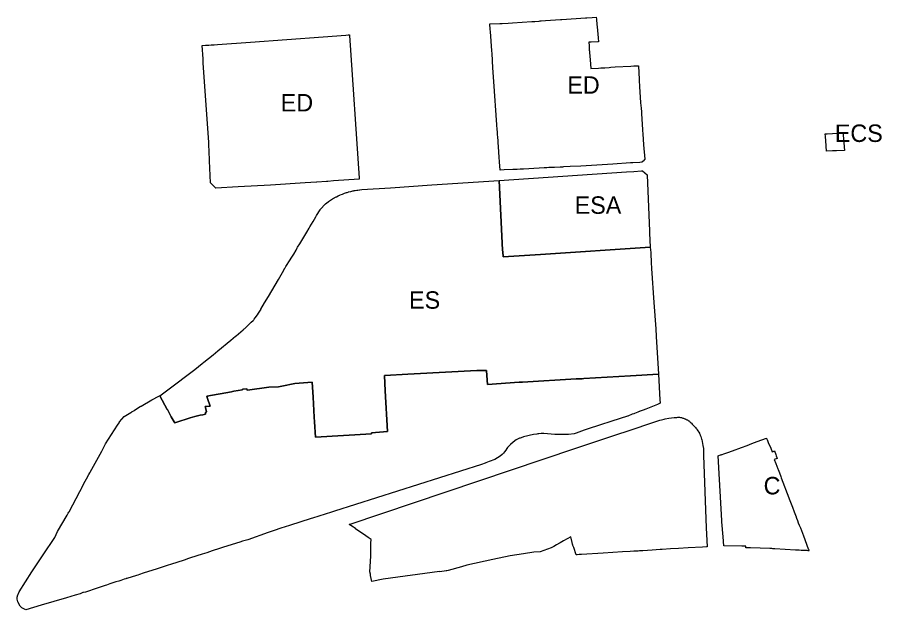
# Model space of a CAD drawing. Extents: x 603332 to 610661, y 4407453 to 4413433.
# Drawn here: x 607136 to 607730, y 4411318 to 4411725 of the extents above; entities that cross this region are included whole.
import ezdxf

# ---------------------------------------------------------------- set-up
doc = ezdxf.new("R2010")
doc.units = 0
for name, color, linetype in [('Sistema General-Equipament Públic Cementiri', 7, 'Continuous'), ('Sistema General-Equipament Públic Docent', 7, 'Continuous'), ('Sistema General-Equipament Públic Esportiu', 7, 'Continuous'), ('Sistema General-Equipament Públic Sanitari-Assistencial', 7, 'Continuous'), ('Sistema General-Equipament Públic Socio-cultural', 7, 'Continuous'), ('Sistema General-Espai Lliure Públic', 7, 'Continuous')]:
    doc.layers.add(name, color=color, linetype=linetype)

msp = doc.modelspace()

# ---------------------------------------------------------------- linework, layer by layer
at = {"layer": 'Sistema General-Equipament Públic Cementiri'}
msp.add_lwpolyline([(607668.26, 4411389.42), (607668.72, 4411388.22), (607669.92, 4411385.07), (607671.21, 4411381.68), (607671.37, 4411381.29), (607671.57, 4411380.76), (607671.58, 4411380.73), (607671.59, 4411380.69), (607671.63, 4411380.6), (607672.19, 4411379.13), (607672.78, 4411377.6), (607673.24, 4411376.38), (607673.35, 4411376.09), (607673.47, 4411375.79), (607674.17, 4411373.96), (607676.25, 4411368.51), (607679.65, 4411359.62), (607679.77, 4411359.3), (607680.01, 4411358.68), (607680.11, 4411358.4), (607680.14, 4411358.35), (607680.15, 4411358.32), (607679.74, 4411358.34), (607679.73, 4411358.34), (607679.69, 4411358.34), (607679.63, 4411358.34), (607679.44, 4411358.35), (607678.77, 4411358.38), (607676.82, 4411358.46), (607675.36, 4411358.53), (607675.31, 4411358.53), (607675.25, 4411358.53), (607675.06, 4411358.54), (607674.93, 4411358.55), (607674.84, 4411358.55), (607673.45, 4411358.64), (607670.81, 4411358.8), (607656.64, 4411359.66), (607656.59, 4411359.66), (607656.56, 4411359.66), (607656.45, 4411359.67), (607656.42, 4411359.67), (607656.41, 4411359.67), (607656.41, 4411359.67), (607655.31, 4411359.71), (607654.49, 4411359.74), (607653.2, 4411359.78), (607639.79, 4411360.25), (607639.39, 4411360.25), (607639.09, 4411360.26), (607639.07, 4411360.26), (607639.05, 4411360.26), (607639.03, 4411360.26), (607638.62, 4411360.26), (607636.73, 4411360.29), (607636.62, 4411360.29), (607636.62, 4411360.4), (607636.62, 4411360.66), (607636.63, 4411361.39), (607636.62, 4411361.39), (607636.6, 4411361.39), (607636.6, 4411361.39), (607636.49, 4411361.39), (607636.42, 4411361.39), (607636.4, 4411361.39), (607636.3, 4411361.39), (607636.05, 4411361.4), (607635.17, 4411361.41), (607634.36, 4411361.41), (607633.87, 4411361.42), (607621.48, 4411361.67), (607621.03, 4411367.87), (607620.29, 4411378.21), (607620.29, 4411378.23), (607620.28, 4411378.26), (607620.28, 4411378.31), (607620.25, 4411379.05), (607618.56, 4411407.27), (607617.66, 4411423.64), (607618.11, 4411423.78), (607619.33, 4411424.16), (607619.41, 4411424.18), (607619.47, 4411424.2), (607619.62, 4411424.25), (607620.26, 4411424.44), (607620.31, 4411424.46), (607621.56, 4411424.84), (607624.41, 4411425.9), (607627.44, 4411427.03), (607633.8, 4411429.4), (607637.49, 4411430.78), (607640.76, 4411432), (607644.38, 4411433.35), (607650.9, 4411435.78), (607650.99, 4411435.56), (607651.22, 4411435.02), (607651.28, 4411434.88), (607652.15, 4411432.77), (607653.82, 4411428.75), (607654.82, 4411426.34), (607655.15, 4411426.47), (607655.39, 4411426.57), (607655.95, 4411426.8), (607656.13, 4411426.87), (607656.31, 4411426.94), (607657.22, 4411424.52), (607657.56, 4411423.6), (607657.98, 4411422.46), (607658.23, 4411421.8), (607656.21, 4411421.12), (607657.33, 4411418.18), (607658.67, 4411414.63), (607658.85, 4411414.17), (607659.72, 4411411.86), (607660.7, 4411409.3), (607661.05, 4411408.36), (607666.27, 4411394.62), (607666.54, 4411393.91)], close=True, dxfattribs=at)
at = {"layer": 'Sistema General-Equipament Públic Docent'}
for points in [[(607562.79, 4411691.82), (607563.3, 4411682.32), (607563.34, 4411681.68), (607563.41, 4411680.54), (607563.52, 4411678.75), (607563.58, 4411677.87), (607563.6, 4411677.53), (607563.6, 4411677.5), (607564.34, 4411666.39), (607564.64, 4411662.64), (607564.84, 4411660.06), (607564.91, 4411658.93), (607565.6, 4411647.69), (607565.63, 4411647.34), (607565.82, 4411644.87), (607566.37, 4411637.4), (607567.13, 4411627.65), (607565.99, 4411626.29), (607565.47, 4411625.66), (607565.35, 4411625.51), (607565.26, 4411625.41), (607565.25, 4411625.41), (607565.17, 4411625.4), (607563.83, 4411625.33), (607559.03, 4411625.05), (607558.42, 4411625.01), (607557.45, 4411624.95), (607545.32, 4411624.19), (607537.89, 4411623.72), (607523.27, 4411622.83), (607515.95, 4411622.43), (607511.22, 4411622.18), (607510.72, 4411622.15), (607509.04, 4411622.06), (607505.16, 4411621.93), (607505.09, 4411621.93), (607505, 4411621.92), (607504.14, 4411621.88), (607503.25, 4411621.84), (607501.18, 4411621.73), (607499.85, 4411621.66), (607499.21, 4411621.62), (607498.03, 4411621.56), (607487.41, 4411620.88), (607483.81, 4411620.72), (607482.93, 4411620.68), (607482.63, 4411620.67), (607482.6, 4411620.67), (607481.5, 4411620.62), (607479.41, 4411620.53), (607478.22, 4411620.48), (607476.42, 4411620.4), (607470.59, 4411620.14), (607467.71, 4411620.02), (607467.3, 4411625.61), (607467.06, 4411628.93), (607467.04, 4411629.14), (607467.04, 4411629.16), (607467.04, 4411629.21), (607467.02, 4411629.42), (607466.85, 4411631.85), (607466.49, 4411636.69), (607466.4, 4411638.22), (607466.29, 4411640.15), (607466.27, 4411640.37), (607466.27, 4411640.41), (607466.11, 4411642.41), (607465.93, 4411644.73), (607465.81, 4411646.34), (607465.68, 4411647.98), (607465.5, 4411651.13), (607463.45, 4411681.02), (607462.81, 4411690.28), (607462.13, 4411700.26), (607462, 4411702.1), (607461.09, 4411715.36), (607460.83, 4411716.76), (607460.65, 4411720.54), (607467.59, 4411720.86), (607468.11, 4411720.85), (607468.93, 4411720.84), (607469, 4411720.84), (607469.01, 4411720.84), (607473.34, 4411721.08), (607476.18, 4411721.28), (607489.46, 4411722.19), (607489.81, 4411722.22), (607491.48, 4411722.33), (607494.62, 4411722.54), (607495.24, 4411722.58), (607495.89, 4411722.63), (607495.98, 4411722.63), (607498.94, 4411722.83), (607509.15, 4411723.52), (607510.09, 4411723.58), (607510.2, 4411723.59), (607526.33, 4411724.66), (607526.44, 4411724.67), (607527.39, 4411724.72), (607531.11, 4411724.95), (607533.84, 4411725.12), (607533.96, 4411723.87), (607534.1, 4411722.43), (607534.2, 4411721.41), (607534.32, 4411720.2), (607534.47, 4411718.63), (607535.22, 4411710.93), (607535.47, 4411708.35), (607535.13, 4411708.33), (607535.09, 4411708.33), (607534.79, 4411708.32), (607530.38, 4411708.11), (607528.69, 4411707.93), (607528.84, 4411705.41), (607528.97, 4411703.25), (607529.05, 4411702.27), (607529.06, 4411702.04), (607529.15, 4411700.93), (607529.54, 4411695.89), (607530.01, 4411689.83), (607535.44, 4411690.19), (607537.03, 4411690.29), (607539.68, 4411690.47), (607542.73, 4411690.67), (607543.83, 4411690.75), (607546.72, 4411690.94), (607557.58, 4411691.53), (607559.63, 4411691.67), (607559.72, 4411691.67), (607559.75, 4411691.67), (607560.73, 4411691.74), (607561.06, 4411691.75)], [(607341.74, 4411611.82), (607341.53, 4411611.81), (607333.63, 4411611.29), (607309.9, 4411609.74), (607287.46, 4411608.53), (607272.21, 4411607.7), (607268.59, 4411611.25), (607267.88, 4411626.39), (607267.55, 4411633.38), (607267.39, 4411636.95), (607267.33, 4411638.07), (607267.29, 4411638.91), (607263.59, 4411693.9), (607263.59, 4411693.92), (607263.42, 4411696.45), (607262.8, 4411705.68), (607265.01, 4411705.84), (607266.34, 4411705.94), (607267.43, 4411706.02), (607269.01, 4411706.13), (607269.04, 4411706.13), (607269.18, 4411706.14), (607269.42, 4411706.16), (607270.47, 4411706.24), (607270.8, 4411706.26), (607270.84, 4411706.26), (607271.07, 4411706.28), (607273.46, 4411706.46), (607296.11, 4411708.1), (607346.13, 4411711.74), (607361.68, 4411712.87), (607363.18, 4411712.98), (607363.4, 4411713), (607363.44, 4411713), (607363.54, 4411713.01), (607363.79, 4411713.03), (607364.14, 4411713.06), (607364.16, 4411713.06), (607364.19, 4411713.06), (607364.22, 4411712.7), (607364.22, 4411712.64), (607370.81, 4411614.38), (607370.82, 4411614.09), (607370.85, 4411613.73), (607353.16, 4411612.57), (607349.26, 4411612.31), (607348.42, 4411612.26)]]:
    msp.add_lwpolyline(points, close=True, dxfattribs=at)
at = {"layer": 'Sistema General-Equipament Públic Esportiu'}
msp.add_lwpolyline([(607570.95, 4411567.15), (607571.24, 4411563.39), (607571.29, 4411562.65), (607571.65, 4411556.59), (607571.6, 4411556.59), (607571.88, 4411552.43), (607573.44, 4411529.06), (607574.77, 4411510.81), (607575.07, 4411505.67), (607576.6, 4411479.75), (607557.26, 4411478.49), (607525.32, 4411476.72), (607524.15, 4411476.59), (607519.94, 4411476.43), (607483, 4411474.27), (607480.92, 4411474.12), (607458.93, 4411472.72), (607458.47, 4411478.9), (607458.26, 4411482.29), (607451.77, 4411482.14), (607408.49, 4411479.88), (607404.33, 4411479.67), (607388.51, 4411478.84), (607388.13, 4411478.82), (607388.7, 4411468.25), (607390.21, 4411440.25), (607379.27, 4411439.48), (607379.36, 4411438.69), (607340.66, 4411436.48), (607340.07, 4411446.9), (607339.89, 4411450.16), (607339.11, 4411463.87), (607338.51, 4411474.31), (607326.47, 4411473.32), (607324.35, 4411472.76), (607319.78, 4411471.86), (607315.4, 4411471), (607308.67, 4411470.84), (607293.95, 4411468.74), (607293.19, 4411469.68), (607290.54, 4411469.34), (607290.57, 4411468.93), (607284.6, 4411467.98), (607283.76, 4411467.72), (607282.93, 4411467.58), (607265.96, 4411464.59), (607266.49, 4411462.93), (607268.36, 4411457.71), (607264.83, 4411457.4), (607265.83, 4411453.96), (607265.83, 4411453.95), (607265.19, 4411453.1), (607265.15, 4411452.59), (607265.1, 4411452.11), (607263.21, 4411451.8), (607261.39, 4411451.5), (607257.86, 4411450.56), (607254.67, 4411449.71), (607244.64, 4411446.46), (607243.99, 4411446.24), (607243.48, 4411447.02), (607241.55, 4411450.48), (607238.86, 4411455.32), (607238.85, 4411455.32), (607238.83, 4411455.35), (607238.8, 4411455.41), (607233.59, 4411464.82), (607239.22, 4411469.04), (607257.7, 4411482.88), (607262.72, 4411486.95), (607264.06, 4411488.04), (607270.31, 4411493.11), (607273.67, 4411495.87), (607282.49, 4411503.11), (607285.77, 4411505.8), (607286.19, 4411506.16), (607287.71, 4411507.45), (607290.92, 4411510.17), (607291.68, 4411510.82), (607292.11, 4411511.18), (607296.52, 4411515.47), (607297.8, 4411516.7), (607298.3, 4411517.17), (607298.51, 4411517.45), (607299.23, 4411518.4), (607300.9, 4411520.59), (607301.57, 4411521.65), (607302.93, 4411523.8), (607303.08, 4411524.05), (607303.26, 4411524.33), (607305.78, 4411528.67), (607308.39, 4411533.15), (607315.22, 4411544.9), (607318.02, 4411549.7), (607319.45, 4411552.16), (607319.48, 4411552.22), (607319.52, 4411552.29), (607319.53, 4411552.31), (607319.54, 4411552.32), (607319.84, 4411552.77), (607319.9, 4411552.86), (607319.9, 4411552.86), (607319.95, 4411552.93), (607320.17, 4411553.27), (607320.45, 4411553.69), (607323.3, 4411558.36), (607324.04, 4411559.57), (607325.74, 4411562.34), (607327.34, 4411564.89), (607328.16, 4411566.54), (607328.45, 4411567.02), (607329.87, 4411569.36), (607333.3, 4411575.04), (607334.71, 4411577.38), (607336.29, 4411580.02), (607336.92, 4411581.06), (607339.08, 4411584.66), (607340.9, 4411587.97), (607341.45, 4411588.82), (607343.93, 4411592.67), (607344.03, 4411592.83), (607344.04, 4411592.84), (607344.27, 4411593.11), (607347.37, 4411596.62), (607347.39, 4411596.63), (607347.57, 4411596.78), (607348.57, 4411597.57), (607349.35, 4411598.14), (607349.72, 4411598.41), (607349.8, 4411598.47), (607351.06, 4411599.34), (607351.83, 4411599.83), (607352.28, 4411600.11), (607352.35, 4411600.16), (607352.36, 4411600.16), (607352.41, 4411600.19), (607353.42, 4411600.79), (607353.53, 4411600.85), (607353.58, 4411600.88), (607353.67, 4411600.94), (607354.94, 4411601.62), (607355.02, 4411601.66), (607355.02, 4411601.67), (607355.02, 4411601.67), (607355.13, 4411601.72), (607356.39, 4411602.35), (607356.69, 4411602.49), (607357.5, 4411602.86), (607357.78, 4411602.99), (607359.2, 4411603.57), (607360.63, 4411604.11), (607362.08, 4411604.6), (607362.53, 4411604.74), (607363.28, 4411604.96), (607363.55, 4411605.04), (607365.03, 4411605.43), (607366.52, 4411605.76), (607366.89, 4411605.83), (607367.26, 4411605.9), (607368.02, 4411606.05), (607369.12, 4411606.22), (607369.46, 4411606.27), (607369.54, 4411606.28), (607369.6, 4411606.29), (607369.9, 4411606.33), (607371.06, 4411606.46), (607371.1, 4411606.47), (607371.33, 4411606.49), (607372.58, 4411606.59), (607392.29, 4411607.91), (607420.86, 4411609.83), (607466.98, 4411612.91), (607469.39, 4411565.04), (607469.47, 4411563.86), (607469.69, 4411560.44), (607495.37, 4411562.09)], close=True, dxfattribs=at)
at = {"layer": 'Sistema General-Equipament Públic Sanitari-Assistencial'}
msp.add_lwpolyline([(607568.79, 4411616.73), (607570.45, 4411578.09), (607570.7, 4411570.59), (607570.74, 4411569.85), (607570.74, 4411569.82), (607570.78, 4411569.33), (607570.89, 4411567.87), (607570.95, 4411567.15), (607495.37, 4411562.09), (607469.69, 4411560.44), (607469.47, 4411563.86), (607469.39, 4411565.04), (607466.98, 4411612.91), (607554.67, 4411618.79), (607559.64, 4411619.12), (607564.92, 4411619.48), (607565.67, 4411619.53)], close=True, dxfattribs=at)
at = {"layer": 'Sistema General-Equipament Públic Socio-cultural'}
msp.add_lwpolyline([(607692.15, 4411633.02), (607692.15, 4411633.03), (607691.61, 4411640.09), (607691.38, 4411643.22), (607691.25, 4411644.91), (607692.57, 4411644.99), (607703.54, 4411645.75), (607703.54, 4411645.74), (607703.6, 4411644.89), (607703.66, 4411644.12), (607704.48, 4411633.56), (607699.04, 4411633.32), (607696.78, 4411633.23), (607696.18, 4411633.2)], close=True, dxfattribs=at)
at = {"layer": 'Sistema General-Espai Lliure Públic'}
for points in [[(607181.1, 4411329.54), (607180.99, 4411329.51), (607180.84, 4411329.48), (607178.9, 4411328.78), (607175.52, 4411327.78), (607169.44, 4411325.99), (607152.19, 4411320.91), (607141.47, 4411317.75), (607138.9, 4411319.12), (607137.68, 4411320.23), (607136.13, 4411323.14), (607135.67, 4411325.11), (607135.69, 4411326), (607135.7, 4411326.35), (607135.82, 4411327.04), (607135.86, 4411327.28), (607137.05, 4411330.01), (607145.61, 4411343.85), (607147.47, 4411346.49), (607149.86, 4411349.88), (607153.49, 4411355.39), (607161.42, 4411367.45), (607163.38, 4411371.57), (607169.93, 4411382.65), (607170.74, 4411384.16), (607171.07, 4411384.78), (607171.24, 4411385.09), (607178.64, 4411398.93), (607179.61, 4411400.71), (607179.88, 4411401.21), (607179.9, 4411401.24), (607179.92, 4411401.28), (607182.46, 4411406.1), (607183.37, 4411407.81), (607184.92, 4411410.75), (607185.46, 4411411.78), (607185.7, 4411412.27), (607193.72, 4411426.73), (607193.73, 4411426.75), (607193.79, 4411426.87), (607194.63, 4411428.54), (607196.32, 4411431.88), (607204.5, 4411444.7), (607205.63, 4411446.3), (607205.85, 4411446.61), (607205.89, 4411446.66), (607206.01, 4411446.83), (607209.17, 4411450.5), (607213.7, 4411453.31), (607214.24, 4411453.64), (607214.48, 4411453.79), (607214.64, 4411453.89), (607214.74, 4411453.95), (607215.74, 4411454.58), (607216.08, 4411454.8), (607218.44, 4411456.28), (607220.23, 4411457.41), (607220.55, 4411457.6), (607220.57, 4411457.62), (607220.57, 4411457.62), (607220.69, 4411457.69), (607220.82, 4411457.76), (607228.28, 4411462.04), (607233.1, 4411464.56), (607233.47, 4411464.75), (607233.57, 4411464.81), (607233.57, 4411464.81), (607233.59, 4411464.82), (607238.8, 4411455.41), (607238.83, 4411455.35), (607238.85, 4411455.32), (607238.86, 4411455.32), (607241.55, 4411450.48), (607243.48, 4411447.02), (607243.99, 4411446.24), (607244.64, 4411446.46), (607254.67, 4411449.71), (607257.86, 4411450.56), (607261.39, 4411451.5), (607263.21, 4411451.8), (607265.1, 4411452.11), (607265.15, 4411452.59), (607265.19, 4411453.1), (607265.83, 4411453.95), (607265.83, 4411453.96), (607264.83, 4411457.4), (607268.36, 4411457.71), (607266.49, 4411462.93), (607265.96, 4411464.59), (607282.93, 4411467.58), (607283.76, 4411467.72), (607284.6, 4411467.98), (607290.57, 4411468.93), (607290.54, 4411469.34), (607293.19, 4411469.68), (607293.95, 4411468.74), (607308.67, 4411470.84), (607315.4, 4411471), (607319.78, 4411471.86), (607324.35, 4411472.76), (607326.47, 4411473.32), (607338.51, 4411474.31), (607339.11, 4411463.87), (607339.89, 4411450.16), (607340.07, 4411446.9), (607340.66, 4411436.48), (607379.36, 4411438.69), (607379.27, 4411439.48), (607390.21, 4411440.25), (607388.7, 4411468.25), (607388.13, 4411478.82), (607388.51, 4411478.84), (607404.33, 4411479.67), (607408.49, 4411479.88), (607451.77, 4411482.14), (607458.26, 4411482.29), (607458.47, 4411478.9), (607458.93, 4411472.72), (607480.92, 4411474.12), (607483, 4411474.27), (607519.94, 4411476.43), (607524.15, 4411476.59), (607525.32, 4411476.72), (607557.26, 4411478.49), (607576.6, 4411479.75), (607577.64, 4411462.03), (607577.77, 4411459.94), (607577.69, 4411459.89), (607575.9, 4411458.86), (607567.86, 4411455.74), (607567.81, 4411455.72), (607566.15, 4411455.07), (607566.1, 4411455.05), (607564.02, 4411454.24), (607563.46, 4411454.03), (607563.25, 4411453.95), (607562.5, 4411453.65), (607561.22, 4411453.16), (607560.17, 4411452.75), (607559.59, 4411452.53), (607558.6, 4411452.14), (607555.51, 4411450.95), (607555.23, 4411450.84), (607544.6, 4411447.38), (607536.02, 4411444.58), (607528.32, 4411442.07), (607525.52, 4411441.13), (607519.93, 4411439.25), (607518.55, 4411438.79), (607514.65, 4411438.21), (607507.31, 4411438.16), (607505.4, 4411438.33), (607500.31, 4411438.77), (607497.79, 4411438.99), (607495.85, 4411438.82), (607494.29, 4411438.68), (607493.89, 4411438.65), (607493.72, 4411438.62), (607492.96, 4411438.5), (607490.6, 4411438.13), (607483.82, 4411436.52), (607483.41, 4411436.43), (607483.34, 4411436.41), (607483.27, 4411436.39), (607481.44, 4411435.78), (607480.95, 4411435.62), (607478.71, 4411434.5), (607476.64, 4411433.07), (607474.78, 4411431.41), (607473.08, 4411429.59), (607472.82, 4411429.28), (607472.78, 4411429.23), (607472.31, 4411428.66), (607471.55, 4411427.53), (607470.81, 4411426.42), (607470.11, 4411425.38), (607469.84, 4411425.15), (607469.03, 4411424.47), (607467.67, 4411423.33), (607463.96, 4411421.01), (607460.21, 4411419.64), (607457.99, 4411418.8), (607457.35, 4411418.57), (607454.83, 4411417.62), (607353.91, 4411385.61), (607353.74, 4411385.56), (607351.77, 4411384.93), (607338.75, 4411380.8), (607338.74, 4411380.8), (607337.88, 4411380.44), (607322.77, 4411375.72), (607316.95, 4411373.9), (607315.64, 4411373.44), (607313.65, 4411372.73), (607308.11, 4411370.74), (607294.11, 4411365.71), (607290.54, 4411364.79), (607288.77, 4411364.23), (607277.43, 4411360.75), (607274.78, 4411359.89), (607269.8, 4411358.26), (607266.06, 4411356.95), (607262.79, 4411356.04), (607254.84, 4411353.48), (607253.49, 4411352.99), (607250.48, 4411351.9), (607240.99, 4411348.85), (607239.39, 4411348.32), (607231.85, 4411345.82), (607222.27, 4411342.79), (607219.76, 4411341.95), (607218.55, 4411341.54), (607217.55, 4411341.24), (607211.01, 4411339.3), (607210.45, 4411339.11), (607210.34, 4411339.07), (607209.26, 4411338.69), (607206.88, 4411337.87), (607205.55, 4411337.45), (607203.51, 4411336.81), (607202.12, 4411336.38), (607199.2, 4411335.46), (607196.95, 4411334.71), (607196.05, 4411334.41), (607194.66, 4411333.94), (607190.56, 4411332.57), (607182.67, 4411329.86)], [(607609.99, 4411361.04), (607609.53, 4411361.02), (607606.98, 4411360.86), (607597.12, 4411360.25), (607590.3, 4411359.83), (607584.93, 4411359.5), (607579.14, 4411359.14), (607577.73, 4411359.05), (607572.25, 4411358.71), (607565.76, 4411358.31), (607563.67, 4411358.18), (607562.59, 4411358.11), (607560.1, 4411357.96), (607559.67, 4411357.93), (607557.07, 4411357.77), (607551.79, 4411357.45), (607538.62, 4411356.63), (607523.72, 4411355.73), (607522.14, 4411355.63), (607520.67, 4411355.54), (607520.32, 4411355.52), (607520.3, 4411355.52), (607520.19, 4411355.51), (607520.07, 4411355.5), (607518.34, 4411360.45), (607517.79, 4411362), (607517.72, 4411362.21), (607517.55, 4411362.91), (607517.29, 4411363.93), (607516.31, 4411367.88), (607511.24, 4411365.02), (607508.94, 4411363.73), (607508.48, 4411363.47), (607506.47, 4411362.34), (607504.56, 4411361.27), (607502.86, 4411360.31), (607495.26, 4411357.57), (607490.95, 4411357.37), (607483.87, 4411356.19), (607474.62, 4411354.69), (607462.74, 4411352.19), (607444.9, 4411348.29), (607441.11, 4411347.24), (607432.01, 4411344.72), (607431.08, 4411344.46), (607430.61, 4411344.41), (607429.22, 4411344.25), (607426.06, 4411343.88), (607426.05, 4411344.02), (607387.37, 4411338.83), (607379.47, 4411337.09), (607378.68, 4411341.23), (607378.64, 4411341.43), (607378.49, 4411342.2), (607378.19, 4411343.77), (607378.88, 4411354.48), (607378.83, 4411360.56), (607378.82, 4411362.25), (607378.82, 4411362.36), (607378.82, 4411362.46), (607378.82, 4411362.7), (607378.81, 4411363.55), (607378.94, 4411366.05), (607378.37, 4411366.45), (607377.03, 4411367.37), (607375.47, 4411368.46), (607368.29, 4411373.45), (607368.26, 4411373.47), (607368.22, 4411373.5), (607366.81, 4411374.48), (607364.98, 4411375.75), (607364.04, 4411376.41), (607364.01, 4411376.43), (607519.86, 4411428.87), (607551.43, 4411439.35), (607552.32, 4411439.65), (607577.54, 4411448.02), (607578.74, 4411448.37), (607580.48, 4411448.81), (607581.16, 4411448.98), (607583.62, 4411449.46), (607587.34, 4411449.92), (607587.88, 4411449.96), (607588.59, 4411450), (607589.22, 4411450.03), (607589.83, 4411450.05), (607590.56, 4411450.06), (607591.09, 4411450.07), (607591.64, 4411449.98), (607592.34, 4411449.86), (607593.38, 4411449.48), (607593.4, 4411449.48), (607593.48, 4411449.46), (607593.75, 4411449.38), (607593.87, 4411449.35), (607594.17, 4411449.25), (607594.26, 4411449.23), (607594.33, 4411449.2), (607594.64, 4411449.09), (607595.02, 4411448.94), (607595.27, 4411448.83), (607595.4, 4411448.78), (607595.76, 4411448.6), (607596.11, 4411448.42), (607596.13, 4411448.42), (607596.13, 4411448.41), (607596.48, 4411448.22), (607596.83, 4411448.01), (607597.04, 4411447.87), (607597.17, 4411447.78), (607597.23, 4411447.74), (607597.51, 4411447.55), (607597.83, 4411447.3), (607598.15, 4411447.05), (607598.15, 4411447.04), (607598.46, 4411446.78), (607598.7, 4411446.55), (607598.75, 4411446.5), (607598.89, 4411446.36), (607599.04, 4411446.21), (607599.32, 4411445.92), (607599.86, 4411445.32), (607600.95, 4411444.12), (607600.97, 4411444.1), (607601.07, 4411443.99), (607601.09, 4411443.97), (607601.98, 4411442.99), (607602.61, 4411442.29), (607602.66, 4411442.25), (607602.95, 4411441.87), (607603.32, 4411441.38), (607604.77, 4411439.26), (607604.91, 4411438.92), (607605.25, 4411438.11), (607605.35, 4411437.84), (607605.69, 4411436.92), (607605.72, 4411436.82), (607605.73, 4411436.8), (607606.28, 4411434.97), (607606.28, 4411434.95), (607606.3, 4411434.88), (607606.31, 4411434.82), (607606.32, 4411434.81), (607607.18, 4411430.74), (607607.62, 4411428.68), (607607.62, 4411428.46), (607607.63, 4411427.98), (607607.63, 4411427.83), (607607.67, 4411423.82), (607609.5, 4411374.15)]]:
    msp.add_lwpolyline(points, close=True, dxfattribs=at)

# ---------------------------------------------------------------- texts
at = {"layer": 'Sistema General-Equipament Públic Cementiri'}
msp.add_text('C', height=12, dxfattribs=at).set_placement((607648.9, 4411397.05))
at = {"layer": 'Sistema General-Equipament Públic Docent'}
for p in [(607513.89, 4411672.57), (607316.82, 4411660.38)]:
    msp.add_text('ED', height=12, dxfattribs=at).set_placement(p)
at = {"layer": 'Sistema General-Equipament Públic Esportiu'}
msp.add_text('ES', height=12, dxfattribs=at).set_placement((607405.09, 4411524.7))
at = {"layer": 'Sistema General-Equipament Públic Sanitari-Assistencial'}
msp.add_text('ESA', height=12, dxfattribs=at).set_placement((607518.96, 4411589.98))
at = {"layer": 'Sistema General-Equipament Públic Socio-cultural'}
msp.add_text('ECS', height=12, dxfattribs=at).set_placement((607697.87, 4411639.39))

doc.saveas('drawing.dxf')
